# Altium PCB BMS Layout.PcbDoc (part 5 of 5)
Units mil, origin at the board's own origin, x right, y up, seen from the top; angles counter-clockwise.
Board outline 5576.78 x 4051.82 mil, 6 copper layers (Top Layer, GND1, Analog Signal, Power, GND2, Bottom Layer), stack 61.2 mil thick; 425 components, 206 nets, 1164 pads, 390 vias.
Unrouted connection lines stored in the file: 32.
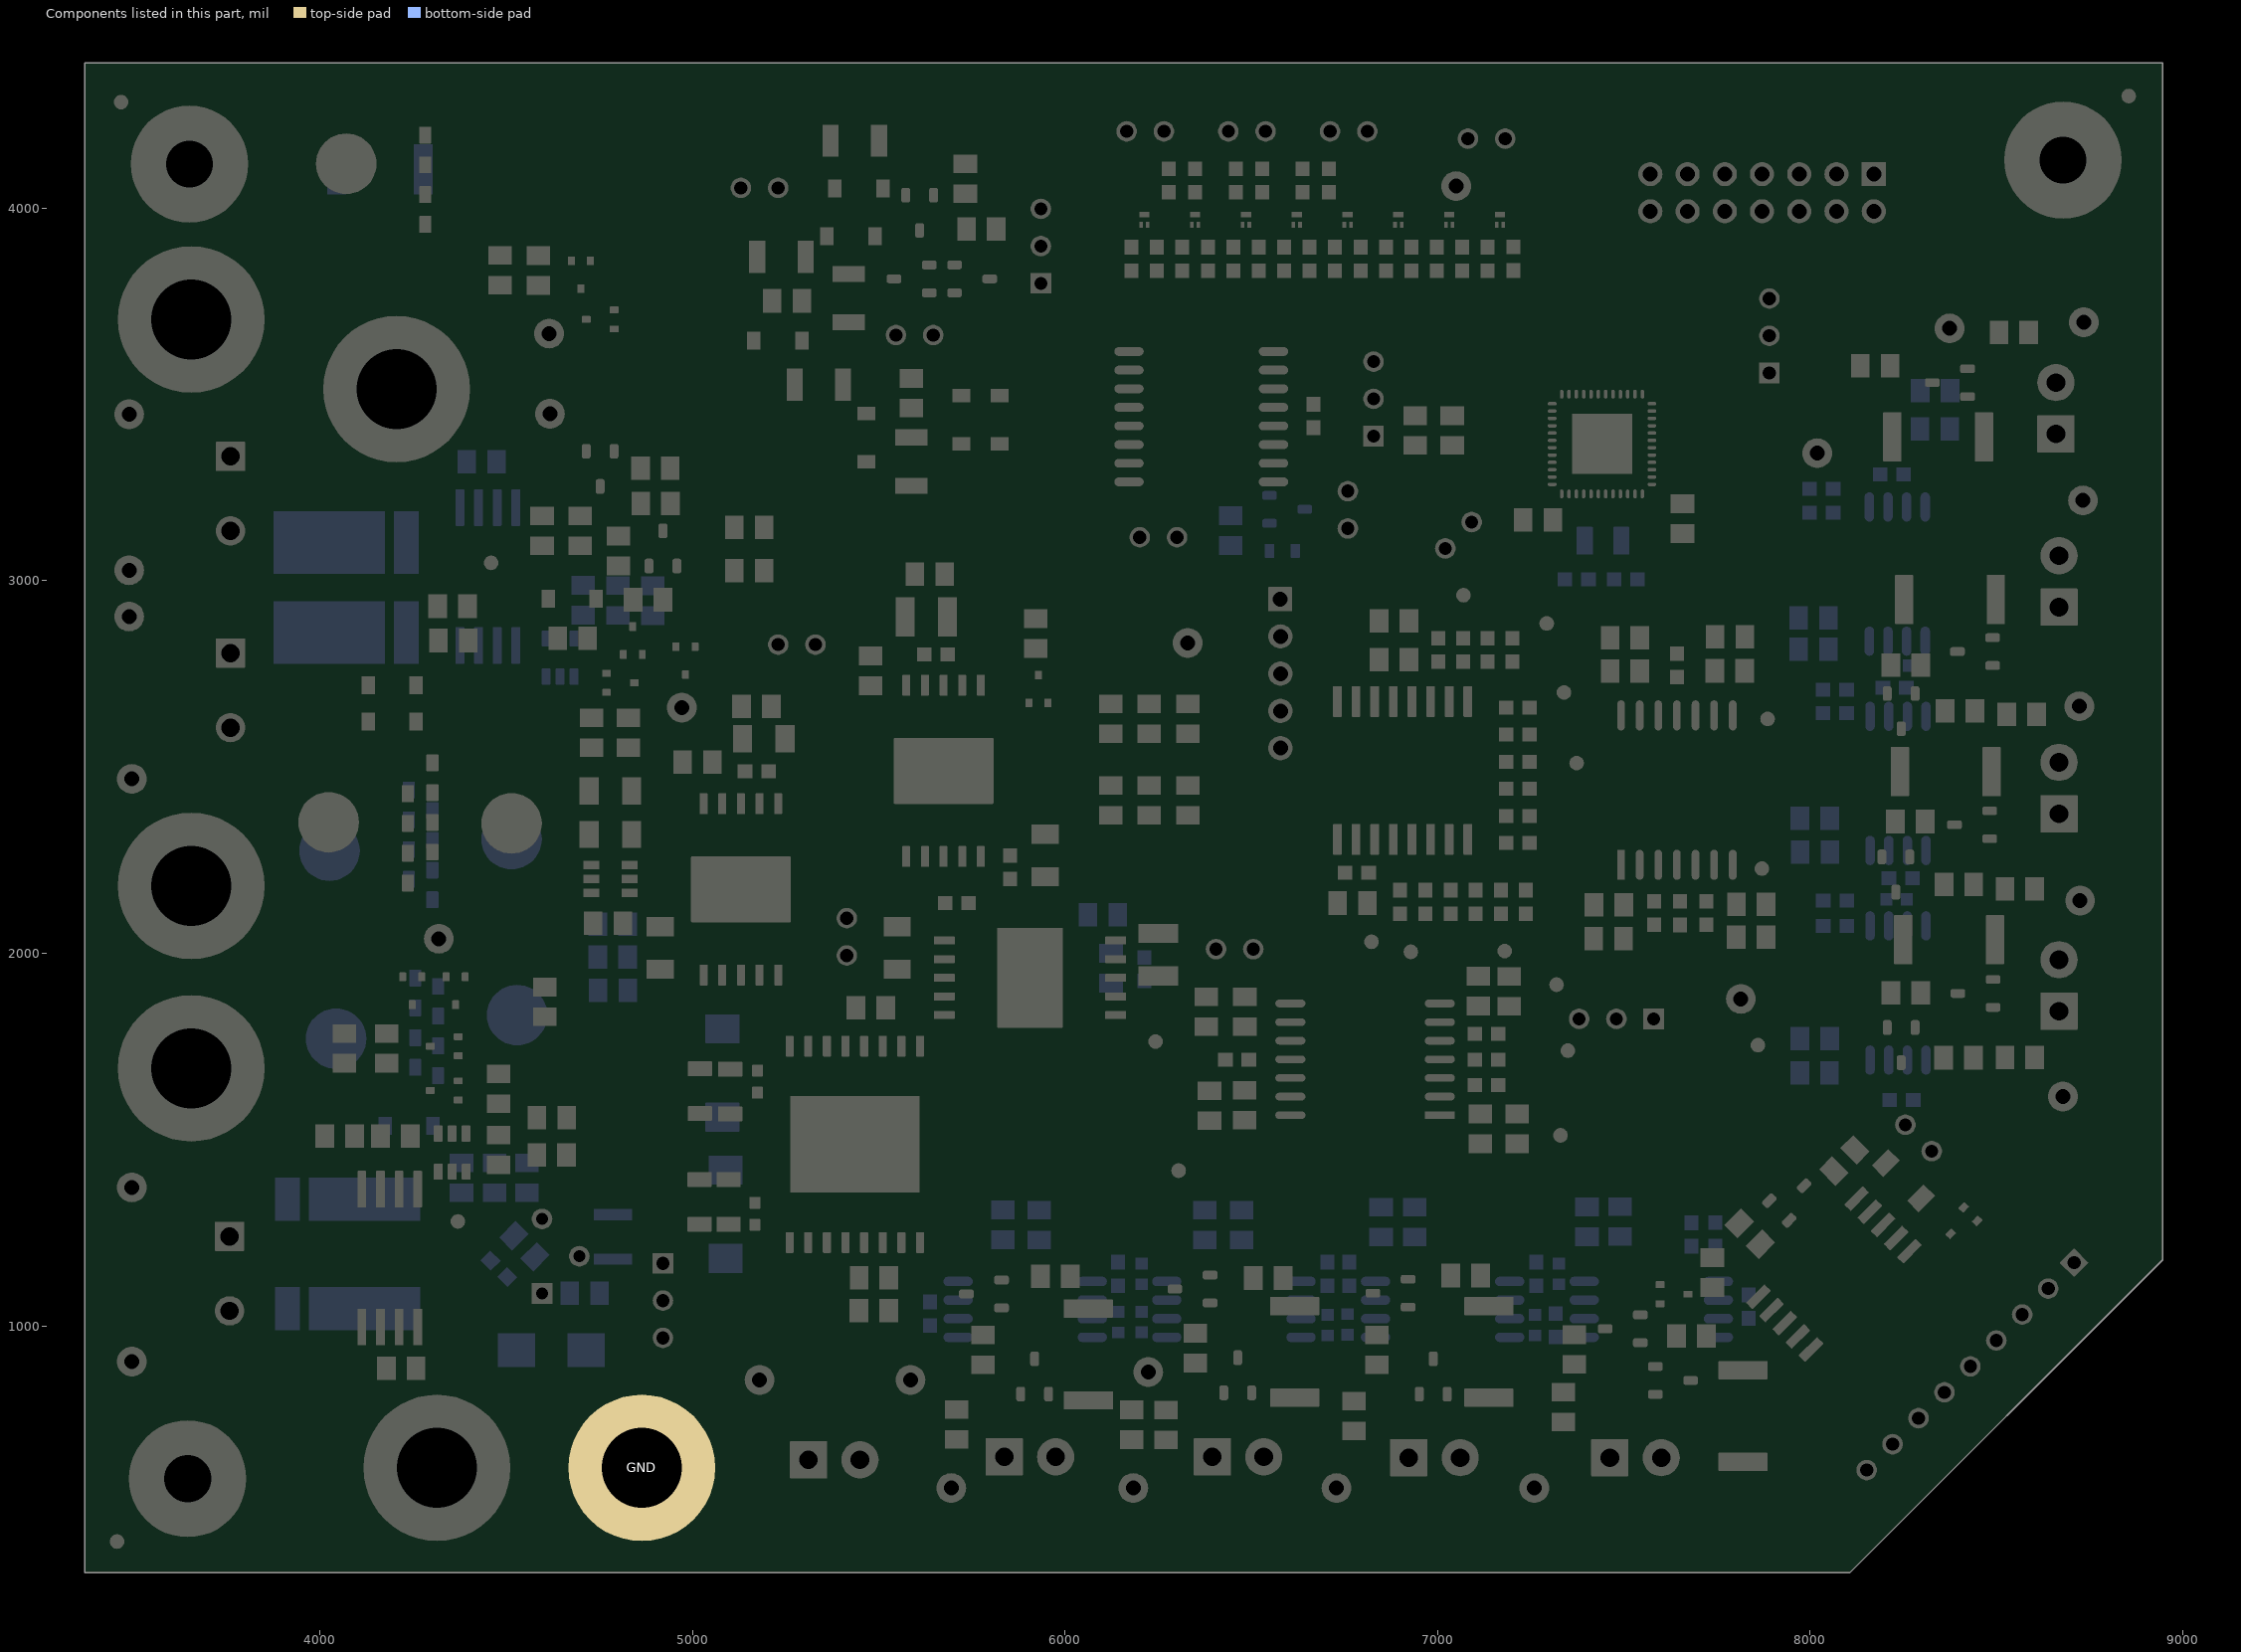
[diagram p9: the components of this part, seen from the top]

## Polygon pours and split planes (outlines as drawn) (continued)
NetC112_1 on Top Layer "NONET_L02_P-001" (solid, pour order 338): 8107.8,1553.93 8059.14,1505.27 8059.14,1476.95 8115.43,1420.67 8115.43,1396.7 8076.94,1358.21 8076.94,1314.64 8097.27,1294.3 8117.24,1294.3 8233.13,1410.2 8329.54,1410.2 8368.39,1449.05 8368.39,1493.65 8345.87,1516.17 8306.13,1516.17 8276.11,1486.14 8216.5,1486.14 8148.71,1553.93
GND on Bottom Layer "NONET_L02_P-001" (solid, pour order 409): 3369.09,4389.76 3369.09,332.49 8102.57,332.49 8949.03,1178.95 8949.03,4389.76
NetLoad_1 on Bottom Layer "NONET_L02_P-001" (solid, pour order 279): 4209.46,4364.27 3394.58,4364.27 3394.58,3274.01 3808.18,3274.01 3939.7,3405.53 3939.7,3639.33 4074.3,3773.93 4209.46,3773.93
NetC15_1 on Bottom Layer "NONET_L02_P-001" (solid, pour order 282): 4414.85,1195.68 4414.85,1159.83 4439.61,1135.07 4467.35,1135.07 4571.68,1239.4 4806.58,1239.4 4851.13,1194.86 4851.13,1144.6 4867.72,1128.01 4958.38,1128.01 4984.96,1154.59 4984.96,1290.46 4935.56,1339.86 4594.88,1339.86 4567.75,1312.73 4531.9,1312.73
Batt1_4V2 on Bottom Layer "NONET_L02_P-001" (solid, pour order 309): 8568.95,1110.98 8568.95,915.98 8618.82,866.12 8636.53,866.12 8946.36,1175.94 8946.36,3325.9 8899.34,3372.91 8633.56,3372.91 8593.4,3332.75 8593.4,3014.55 8651.17,2956.78 8817.01,2956.78 8817.01,2742.63 8817.01,1357.54
Batt3_12V6 on Bottom Layer "NONET_L02_P-001" (solid, pour order 321): 8619.1,2432.66 8596.31,2409.87 8596.31,1971.21 8632.17,1935.35 8712.86,1935.35 8729.63,1918.58 8729.63,1471.59 8401.53,1143.5 8401.53,997.25 8496.21,902.57 8552.86,902.57 8568.95,918.66 8568.95,1110.98 8815.07,1357.1 8815.07,2432.66
Batt7_29V4 on Bottom Layer "NONET_L02_P-001" (solid, pour order 396): 6005.06,693.68 6005.06,344.49 8106.64,344.49 8266.07,498.88 8266.07,730.08 8221.88,731.31 8176.09,685.53 8176.09,573.6 8081.43,478.93 6517.92,478.93 6517.92,693.68
Batt5_21V on Bottom Layer "NONET_L02_P-001" (solid, pour order 398): 7061.47,698.01 7061.47,481.35 7573.87,481.35 7974.06,486.88 8272.26,785.08 8395.72,785.08 8395.72,861.96 8190.67,861.96 7919.96,581.76 7573.87,581.76 7573.87,688.53 7573.87,698.01
Batt_out on Bottom Layer "NONET_L02_P-001" (solid, pour order 407): 3369.77,1463.65 3369.77,340.64 4630.53,340.64 4630.53,1123.97 4553.33,1123.97 4496.73,1067.37 4387.08,1067.37 4255.38,1199.07 3927.91,1199.07 3663.33,1463.65
NetQ23_5 on Bottom Layer "NONET_L02_P-001" (solid, pour order 402): 3866.86,1999.41 3866.86,1517.68 3957.99,1426.55 3957.99,1204.25 4310.2,1204.25 4310.2,1393.05 4240.51,1462.74 4194.72,1462.74 4149.65,1507.81 4149.65,1999.41
NetD6_2 on Bottom Layer "NONET_L02_P-001" (solid, pour order 401): 4192.66,1936.05 4192.66,1657.29 4366.46,1657.29 4366.46,1936.05
NetQ18_5 on Bottom Layer "NONET_L02_P-001" (solid, pour order 399): 3859.99,2976.7 3859.99,2781.91 4358.35,2283.55 4358.35,1622.47 4418.42,1562.4 4681.42,1562.4 4681.42,2647.68 4596.97,2732.14 4231.9,2732.14 4191.01,2773.03 4191.01,2976.22
NetD5_2 on Bottom Layer "NONET_L02_P-001" (solid, pour order 383): 4177.39,2404.64 4177.39,2158.82 4351.18,2158.82 4351.18,2404.64
Charger_Vin on Bottom Layer "NONET_L02_P-001" (solid, pour order 382): 3369.09,2732.14 3369.09,2002.58 4169.29,2002.58 4169.29,2492.69 3929.85,2732.14
NetLoad_2 on Bottom Layer "NONET_L02_P-001" (solid, pour order 380): 4015.86,3754.65 3947.86,3686.65 3947.86,3402.17 3819.69,3274.01 3369.09,3274.01 3369.09,2983.65 4186.55,2983.65 4186.55,3195.31 4291.64,3300.4 4361.16,3300.4 4479.61,3418.84 4479.61,3663.46 4388.41,3754.65
NetC9_1 on Bottom Layer "NONET_L02_P-001" (solid, pour order 375): 5030.82,1867.22 5000.54,1836.95 5000.54,1749.78 5030.3,1720.03 5382.79,1720.03 5461.55,1798.79 5461.55,2019.8 5446.35,2035.01 5385.82,2035.01 5365.03,2014.22 5365.03,1903.77 5328.49,1867.22
12V on Bottom Layer "NONET_L02_P-001" (solid, pour order 351): 4863.79,1125.48 4863.79,1022.32 5208,1022.32 5287.66,1101.99 5356.8,1101.99 5388.67,1133.86 5388.67,1167.2 5314.63,1241.24 4998.33,1241.24 4998.33,1125.48
3.3V on Bottom Layer "NONET_L02_P-001" (solid, pour order 324): 6393.49,3260.28 6384.87,3251.67 6384.87,3152.57 6403.43,3134.01 6482.31,3134.01 6536.66,3188.36 6560.86,3188.36 6583.73,3211.23 6583.73,3247.03 6570.47,3260.28
NetC164_1 on Bottom Layer "NONET_L02_P-001" (solid, pour order 327): 6625.28,3241.77 6587.43,3203.92 6587.43,3058.83 6609.76,3036.51 6649.54,3036.51 6682.54,3069.51 6682.54,3132.62 6741.41,3191.5 6774.14,3191.5 6811.61,3228.97 6811.61,3261.69 6776.91,3296.4 6679.91,3296.4
5Vcc on Power "NONET_L02_P-001" (solid, pour order 336): 4718.34,3982.15 4681.42,3945.23 4681.42,3365.98 4681.42,3319.82 4386.45,3024.85 4386.45,2990.2 4564.24,2812.41 4706.52,2812.41 4706.52,2161.37 4842.97,2161.37 4842.97,1586.01 4483.33,1226.36 4123.45,1586.24 4099.94,1586.24 4023.47,1509.77 4023.47,1278.02 4201.49,1100 4609.68,1100 5335.63,1825.96 6564.85,1825.96 6564.85,2232.96 6538.55,2259.26 6130.5,2259.26 6007.86,2381.89 5521.67,2381.89 5282.73,2620.83 5282.73,3042.25 111903.77,109663.28 5984.25,3776.25 5984.25,3818.73 5820.83,3982.15 5129.42,3982.15
3.3V on Power "NONET_L02_P-001" (solid, pour order 290): 4933.06,2697.61 5984.25,3748.8 5984.25,3855.66 6039.34,3910.75 8157.85,3910.75 8239.99,3828.61 8239.99,3502.43 7778.08,3040.52 7224.26,3040.52 7070.36,3194.41 6344.96,3194.41 5811.38,2660.84 4933.06,2660.84
GND on Power "NONET_L02_P-001" (solid, pour order 363): 3369.09,4389.76 3369.09,332.49 8102.57,332.49 8949.03,1178.95 8949.03,4389.76
pump on Power "NONET_L02_P-001" (solid, pour order 335): 4399.61,4389.76 4399.61,3329.52 4065.85,2995.76 4065.85,1984.18 4323.23,1984.18 4323.23,2709.54 4600.61,2709.54 4600.61,2658.07 4681.42,2658.07 4681.42,2812.41 4553.16,2812.41 4382.25,2983.32 4382.25,3020.65 4681.42,3319.82 4681.42,3945.23 4718.34,3982.15 5129.42,3982.15 5178.86,4031.59 5178.86,4388.07 5177.17,4389.76
Batt_out on Power "NONET_L02_P-001" (solid, pour order 360): 3366.14,1454.17 3836.64,1454.17 4190.81,1100 5570.87,1100 5570.87,796.15 5996.59,796.15 5996.59,338.23 3366.14,334.65
NetQ18_5 on Power "NONET_L02_P-001" (solid, pour order 320): 4600.61,2709.54 4323.23,2709.54 4323.23,1944.18 4646.66,1944.18 4646.66,2649.24 4600.61,2649.24
2.5Vref on Power "NONET_L02_P-001" (solid, pour order 287): 8132.4,3343.71 7609.85,2821.16 7609.85,2219.73 7658.46,2171.12 7658.46,2089.44 7639.88,2070.86 7611.34,2070.86 7558.69,2123.5 7504.65,2123.5 7283.96,1902.82 7192.79,1902.82 7106.69,1816.71 7106.69,1804.75 7153.27,1758.17 7153.27,1734.66 7118.69,1700.08 6767.69,1700.08 6641.81,1825.96 5570.87,1825.96 5570.87,797.87 8553.78,797.87 8937.01,1181.1 8937.01,3343.71
5Vcc on Power "NONET_L02_P-001" (solid, pour order 288): 6386.69,2108.69 6386.69,1825.96 6641.81,1825.96 6767.69,1700.08 7120.52,1700.08 7148.31,1727.87 7148.31,1764.96 7146.48,1764.96 7106.69,1804.75 7106.69,1816.71 7107.32,1816.71 7193.42,1902.82 7283.96,1902.82 7504.65,2123.5 7558.69,2123.5 7611.34,2070.86 7639.88,2070.86 7658.46,2089.44 7658.46,2171.12 7609.85,2219.73 6497.73,2219.73
3.3V_2 on Power "NONET_L02_P-001" (solid, pour order 289): 6682.41,3186.17 6682.41,2990.78 6771.73,2901.46 6933.63,2901.46 7102.41,3070.23 7102.41,3186.17
GND on Analog Signal "NONET_L02_P-001" (solid, pour order 348): 3369.09,4389.76 3369.09,332.49 8102.57,332.49 8949.03,1178.95 8949.03,4389.76
12Vcc on Analog Signal "NONET_L02_P-001" (solid, pour order 291): 5386.85,2202.85 5322.1,2138.11 5322.1,2070.28 5322.1,344.49 8100.39,344.49 8937.01,1181.1 8937.01,3177.02 8907.15,3206.87 7978.82,3206.87 7946.41,3174.46 7946.41,1743.31 7570.03,1366.92 5864.27,1366.92 5786.92,1444.27 5786.92,2138.23 5722.29,2202.85
0V6 on Analog Signal "NONET_L02_P-001" (solid, pour order 339): 4544.02,2953.26 4544.02,2857.18 4557.02,2844.18 4634.08,2844.18 4716.95,2927.06 5086.84,2927.06 5127.2,2967.42 5127.2,3108.26 5114.09,3121.37 4712.13,3121.37
0.6V on Analog Signal "NONET_L02_P-001" (solid, pour order 337): 4185.73,1453.16 4185.73,1354.08 4201.03,1338.79 4544.09,1338.79 4814.16,1608.85 4814.16,2252.33 4707.19,2252.33 4655.26,2200.41 4655.26,1922.7
GND on GND1 "NONET_L02_P-001" (solid, pour order 344): 3369.09,4389.76 3369.09,332.49 8102.57,332.49 8949.03,1178.95 8949.03,4389.76
GND on GND1 "NONET_L02_P-001" (solid, pour order 154): 3369.09,4389.76 3369.09,332.49 8102.57,332.49 8949.03,1178.95 8949.03,4389.76
GND on GND2 "NONET_L02_P-001" (solid, pour order 155): 3369.09,4389.76 3369.09,332.49 8102.57,332.49 8949.03,1178.95 8949.03,4389.76

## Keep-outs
Keep-Out Layer:
  text ".Layer_Name" at 577,-858.49 h60

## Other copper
Top Layer:
  text ".Layer_Name" at 577,-858.49 h60
Bottom Layer:
  text ".Layer_Name" at 577,-858.49 h60

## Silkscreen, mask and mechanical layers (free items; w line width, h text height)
Top Overlay:
  text "GND" at 7123.96,4247.09 h60 r90
  text "D-               D-               D-" at 6245.51,4228.18 h60
  text "TX /  /  / RX" at 7545.33,3861.77 h40 r270
  text "12V /  /  / Buff /  /  / 5V" at 5981.94,3761.49 h40
  text "VCC_Target /  /  / 3V3 /  /  / VCC_Tool" at 7619.85,3541.54 h40
  text "GND /  /  /   SEL  /  /  /   SDA" at 6574.17,3363.19 h40
  text "- /  /  / +" at 3508.51,3006.52 h40
  text "DIN /  /  / DOUT /  /  / SCLK /  /  / CS /  /  / GND" at 6407.41,2549.79 h40
  text "+ /  /  / -" at 3492.8,2442.42 h40
  text "2.5Vref /  /  / ADCin /  /  / Vsens5" at 7286.31,1748.3 h40 r270
  text "Space Graded BMS Design Rev 1" at 6098.29,1268.78 h90
  text "+ /  /  / -" at 3468.21,1003.43 h40
  text "12V_LDO /  /  / Sel /  /  / 12V_Supply" at 4998.33,894.25 h40
  text "+ /  /  / -" at 5526.97,388.03 h40 r90
  text "'.PRJ_Number'.PCB_Rev" at 2383.2,147.04 h108.27
  text "Drill Drawing Layer...they should be just to the right of your board shape" at 6663.39,-275.59 h60
  text ".Layer_Name" at 577,-858.49 h60
Bottom Overlay:
  text ".Layer_Name" at 577,-858.49 h60
Top Paste:
  text ".Layer_Name" at 577,-858.49 h60
Bottom Paste:
  text ".Layer_Name" at 577,-858.49 h60
Top Solder:
  text ".Layer_Name" at 577,-858.49 h60
  text ".Layer_Name" at 577,-858.49 h60
Bottom Solder:
  text ".Layer_Name" at 577,-858.49 h60
Drill Guide:
  text ".Layer_Name" at 577,-858.49 h60
M1 Board Outline:
  text ".Layer_Name" at 577,-858.49 h60
M2 Board Dimensions:
  rectangle: 0,-275 125,-150
  rectangle: 125,-400 500,-275
  lines w7: 0,-275 1000,-275 ; 0,-150 0,-400 1000,-400 1000,-150 ; 125,-400 125,-150 ; 250,-400 250,-150 ; 500,-400 500,-150 ; 750,-400 750,-150
  text ".Layer_Name" at 577,-858.49 h60
M3 3D STEP Top:
  text ".Layer_Name" at 577,-858.49 h60
M4 3D STEP Bottom:
  text ".Layer_Name" at 577,-858.49 h60
M5 Assembly Top:
  lines w10: -292,-930.17 6308,-930.17 ; -292,-726.83 6310,-726.83 ; -292,-523.5 -292,-1133.5 3713,-1133.5 6310,-1133.5 6310,-523.5 -291.5,-523.5 -291.5,-1133.5 1284,-1133.5 ; 2173,-1133.5 2173,-523.5 ; 3440,-726.83 3440,-523.5 ; 4280,-726.83 4280,-523.5 ; 4902,-1140 4902,-937.17
  text "COMPONENTS MARKED 'DNP' SHOULD NOT BE POPULATED." at 1153.5,-318.5 h60
  text "ASSEMBLY VARIANT:" at 1153,-434 h60
  text ".VariantName" at 2189,-434 h60
  text "PCB VIEWED FROM TOP SIDE" at -228.5,-655.67 h60
  text "BOARD #:" at 2248,-655.67 h60
  text ".PRJ_Number" at 2793.5,-655.67 h60
  text "REV:" at 3638,-655.67 h60
  text ".PCB_Rev" at 3929.5,-655.67 h60
  text "SVN REV:" at 4476,-655.67 h60
  text ".VersionControl_RevNumber" at 4982,-655.67 h60
  text "TID #:" at 2248,-859 h60
  text ".TID" at 2793.5,-859 h60
  text "PLOT NAME =" at -228.5,-1064.34 h60
  text ".plot_File_Name" at 577,-1064.34 h60
  text "GENERATED    :" at 2250,-1064.34 h60
  text ".Print_Date" at 3119.5,-1064.34 h60
  text ".Print_Time" at 3848.5,-1064.34 h60
  text "TEXAS INSTRUMENTS" at 5113,-1064.34 h60
M6 Assembly Bottom:
  lines w10: -292.5,-727.33 6309.5,-727.33 ; -290.5,-930.67 6309.5,-930.67 ; 1115.5,-1140.5 1115.5,-937.67 ; 1737.5,-727.33 1737.5,-524 ; 2577.5,-727.33 2577.5,-524 ; 3844.5,-1134 3844.5,-524 ; 4733.5,-1134 6309,-1134 6309,-524 -292.5,-524 -292.5,-1134 2304.5,-1134 6309.5,-1134 6309.5,-524
  text "COMPONENTS MARKED 'DNP' SHOULD NOT BE POPULATED." at 6102,-318 h60
  text ".VariantName" at 5058,-434 h60
  text "ASSEMBLY VARIANT:" at 6097,-434 h60
  text ".VersionControl_RevNumber" at 1035.5,-656.17 h60
  text "SVN REV:" at 1541.5,-656.17 h60
  text ".PCB_Rev" at 2088,-656.17 h60
  text "REV:" at 2379.5,-656.17 h60
  text ".PRJ_Number" at 3224,-656.17 h60
  text "BOARD #:" at 3769.5,-656.17 h60
  text "PCB VIEWED FROM BOTTOM SIDE" at 6246,-656.17 h60
  text ".TID" at 3224,-859.5 h60
  text "TID #:" at 3769.5,-859.5 h60
  text "TEXAS INSTRUMENTS" at 904.5,-1064.84 h60
  text ".Print_Time" at 2169,-1064.84 h60
  text ".Print_Date" at 2898,-1064.84 h60
  text "GENERATED    :" at 3767.5,-1064.84 h60
  text ".plot_File_Name" at 5440.5,-1064.84 h60
  text "PLOT NAME =" at 6246,-1064.84 h60
M9 Title Sheet:
  drawing of 57 lines, arcs and shapes, not listed
  text "1" at 739.84,8036.5 h70
  text "2" at 3235.5,8036.5 h70
  text "3" at 5724.84,8036.5 h70
  text "4" at 8231.51,8036.5 h70
  text "5" at 10730.5,8036.5 h70
  text "6" at 13235.5,8036.5 h70
  text "A" at -416.5,6893.5 h70
  text "A" at 14383.5,6893.5 h70
  text "B" at -416.5,4513.5 h70
  text "B" at 14383.5,4513.5 h70
  text "C" at -416.5,2138.5 h70
  text "C" at 14383.5,2138.5 h70
  text "PROJECT TITLE:" at 11343.5,277.5 h45
  text ".PRJ_Title" at 11393.5,144.17 h70
  text "DESIGNED FOR:" at 11343.5,-23.5 h45
  text ".PRJ_Customer" at 11393.5,-163.5 h70
  text "D" at -416.5,-231.5 h70
  text "D" at 14383.5,-231.5 h70
  text "FILE NAME:" at 11343.5,-323.5 h45
  text ".PCB_File_Name_No_Path" at 11393.5,-443.5 h70
  text "Texas Instruments (TI) and/or its licensors do not warrant the accuracy or completeness of this specification" at 6374,-605.34 h45
  text "ENGINEER:" at 11343.5,-613.5 h45
  text "LAYOUT BY:" at 12848.5,-613.5 h45
  text "or any information contained therein. TI and/or its licensors do not warrant that this design will meet" at 6329.01,-718 h45
  text ".PRJ_Engineer" at 11393.5,-768.49 h70
  text ".PCB_Layout" at 12899,-768.49 h70
  text "the specifications, will be suitable for your application or fit for any particular purpose, or will operate in" at 6329.01,-830.67 h45
  text ".Layer_Name" at 577,-858.49 h60
  text "ALTIUM DESIGNER VERSION:" at 12848.5,-923.5 h45
  text "an implementation. TI and/or its licensors do not warrant that the design is production worthy. You should" at 6329.01,-943.33 h45
  text "completely validate and test your design implementation to confirm the system functionality for your application." at 6374,-1056 h45
  text ".print_Scale" at 11393.5,-1056.83 h70
  text ".Application_BuildNumber" at 12899,-1056.83 h70
  text "1" at 739.84,-1263.5 h70
  text "2" at 3235.5,-1263.5 h70
  text "3" at 5724.84,-1263.5 h70
  text "4" at 8231.51,-1263.5 h70
  text "5" at 10730.5,-1263.5 h70
  text "6" at 13235.5,-1263.5 h70
M10 Fab Notes:
  drawing of 189 lines, arcs and shapes, not listed
  text "DESIGN INFORMATION" at 12382.02,6356.17 h60
  text "MIN. TRACK WIDTH:" at 11737.46,6224.05 h60
  text "8" at 12833.7,6224.05 h60
  text "MIL" at 12988.46,6224.05 h60
  text "7.874" at 12667.32,6102.36 h60
  text "MIN. CLEARANCE:" at 11737.46,6099.92 h60
  text "MIL" at 12988.46,6099.92 h60
  text "MIN. VIA PAD SIZE:" at 11737.46,5975.8 h60
  text "24" at 12803.71,5975.8 h60
  text "MIL" at 12988.46,5975.8 h60
  text "0.05mm (2MIL)" at 12432.46,5845.9 h60
  text "MINIMUM ANNULAR RING" at 11408.23,5837.67 h60
  text "EXTERNAL" at 13140.46,5837.67 h60
  text "PER" at 11608.23,5727.55 h60
  text "IPC-D-275 CLASS 2 LEVEL C" at 11828.23,5727.54 h60
  text "MIL, HOLES" at 13316.46,5627.07 h60
  text "+/-" at 12924,5618.48 h60
  text "+/-" at 13778,5618.48 h60
  text "REGISTRATION TOLERANCES:" at 11408.23,5617.42 h60
  text "METAL" at 12608,5617.42 h60
  text "5" at 13184.2,5617.42 h60
  text "3" at 14017.2,5617.42 h60
  text "MIL" at 14133.46,5617.42 h60
  text "HOLE SIZE TOLERANCE (UNLESS OTHERWISE SPECIFIED):" at 11408.23,5519.1 h60
  text "+/-" at 13778,5516.23 h60
  text "3" at 14017.2,5515.17 h60
  text "MIL" at 14133.46,5515.17 h60
  text "MATERIAL:" at 11333.46,5377.52 h60
  text "FR-4 High Tg" at 12319.9,5249 h60
  text "X" at 12175.46,5241.01 h60
  text "FR-408" at 11754.46,5236.49 h60
  text "OTHER" at 13242.46,5236.49 h60
  text "62 MIL (1.6mm) +/-10%" at 12074.56,5093.46 h60
  text "X" at 11954.46,5091.01 h60
  text "THICKNESS:" at 11408.23,5085.24 h60
  text "OTHER" at 13359.46,5085.24 h60
  text "TOLERANCE:" at 11408.23,4946.92 h60
  text "X" at 12256.46,4946.92 h60
  text "ANSI IPC-6012 TYPE 3 CLASS 2" at 12434.48,4946.92 h60
  text "OTHER +/-" at 12434.46,4802.73 h60
  text "BOW & TWIST:" at 11408.23,4657.54 h60
  text "X" at 12256.46,4657.54 h60
  text "ANSI IPC-6012 TYPE 3 CLASS 2" at 12434.48,4657.54 h60
  text "OTHER +/-" at 12434.46,4510.85 h60
  text "DRILLING:" at 11333.46,4380.23 h60
  text "NC_DRILL FILES" at 13094.46,4275.04 h60
  text "REFERENCE:" at 11408.23,4271.1 h60
  text "X" at 12065.46,4271.01 h60
  text "AS SHOWN" at 12243.46,4271.1 h60
  text "X" at 12966.46,4271.1 h60
  text "OTHER" at 13392.46,4128.85 h60
  text "PTH COPPER THICKNESS:" at 11407.91,4125.32 h60
  text "X" at 12547.14,4125.32 h60
  text "20-30 um" at 12675.14,4125.32 h60
  text "BOARD FINISH:" at 11333.46,3977.73 h60
  text "SILKSCREEN:" at 11488.68,3867.6 h60
  text "X" at 12446.46,3867.6 h60
  text "TOP" at 12563.46,3867.6 h60
  text "X" at 12956.46,3867.6 h60
  text "BOTTOM" at 13074.46,3867.6 h60
  text "SILKSCREEN COLOR:" at 11488.68,3712.41 h60
  text "X" at 12445.46,3712.41 h60
  text "WHITE" at 12563.46,3712.41 h60
  text "OTHER" at 13074.46,3712.41 h60
  text "X" at 12576.46,3568.96 h60
  text "GREEN" at 12694.46,3568.96 h60
  text "OTHER" at 13312.46,3568.96 h60
  text "SOLDER RESIST COLOR:" at 11488.68,3562.1 h60
  text "X" at 12576.46,3414.71 h60
  text "MATTE" at 12694.46,3414.71 h60
  text "SEMI-GLOSS" at 13312,3414.07 h60
  text "IMMERSION GOLD (ENIG)" at 12394.46,3241.94 h60
  text "ENEPIG" at 13732,3234.72 h60
  text "SURFACE FINISH:" at 11333.46,3233.72 h60
  text "X" at 12216.46,3233.72 h60
  text "IMM. TIN/SILVER OR EQUIV" at 11663,3096.4 h60
  text "OTHER" at 13094.46,3092.47 h60
  text "ARRAY/PANEL:" at 11333.46,2937.09 h60
  text "CUT AND TRIM PER M1 BOARD OUTLINE" at 12394.46,2928.87 h60
  text "N.C. ROUTE" at 12394.46,2792.9 h60
  text "X" at 13082.46,2792.9 h60
  text "V. SCORE" at 13260.46,2792.9 h60
  text "CERTIFICATION:" at 11333.46,2663.77 h60
  text "MATERIALS AND WORKMANSHIP FOR ALL PCBS" at 12058.46,2663.77 h60
  text "TO MEET OR EXCEED THE REQUIREMENTS OF:" at 12058.46,2569.71 h60
  text "X" at 11695.97,2441.08 h60
  text "ANSI IPC-A-600F CLASS ->" at 11823.96,2441.08 h60
  text "X" at 13471.97,2441.08 h60
  text "2" at 13581.96,2441.08 h60
  text "1" at 13266.96,2439.58 h60
  text "3" at 13935.96,2439.58 h60
  text "X" at 12507.97,2293.39 h60
  text "RoHS" at 12635.96,2293.39 h60
  text "OTHER" at 13280.36,2293.39 h60
  text "PER ORDER" at 13677.42,2293.39 h60
  text "ALL BOARDS MUST MEET OR EXCEED UL94-V0 REQUIREMENTS." at 11361,2139.57 h60
  text "PCB MUST BEAR THE UL94V-0 UL REGISTERED MATERIAL ID NUMBER" at 11361,2023.5 h60
  text "ADDITIONAL REQUIREMENTS:" at 11333.46,1854.08 h60
  text "MICROSECTION:" at 11408.23,1746.95 h60
  text "YES" at 12313.96,1746.95 h60
  text "REQUIRED" at 13175.46,1602.62 h60
  text "BARE BOARD ELEC. TEST:" at 11408.23,1599.76 h60
  text "NONE" at 12713.96,1599.76 h60
  text "X" at 13057.46,1599.76 h60
  text "PER ORDER" at 13767.46,1599.76 h60
  text "XX MIL VIAS REQUIRE NON-CONDUCTIVE FILL AND PLANARIZE" at 11576.38,1394.82 h59
  text "XX MIL VIAS REQUIRE CONDUCTIVE FILL AND PLANARIZE" at 11584.38,1290.84 h60
  text "OUTER XX MIL TRACES REQUIRE 50 OHM SINGLE-ENDED IMPEDANCE" at 11583.39,1127.46 h58
  text "LAYER 2 & 3 (INNER LAYERS) XX MIL WIDE, XX MIL SPACE / TRACES REQUIRE 100 OHM DIFFERENTIAL IMPEDANCE" at 11575.39,891.74 h60
  text ".Layer_Name" at 577,-858.49 h60
M11 Gerber Information:
  lines w10: -292,-930.17 6308,-930.17 ; -292,-726.83 6310,-726.83 ; -292,-523.5 -292,-1133.5 3713,-1133.5 6310,-1133.5 6310,-523.5 -291.5,-523.5 -291.5,-1133.5 1284,-1133.5 ; 2173,-1133.5 2173,-523.5 ; 3440,-726.83 3440,-523.5 ; 4280,-726.83 4280,-523.5 ; 4902,-1140 4902,-937.17
  text "ALL ARTWORK VIEWED FROM TOP SIDE" at -228.5,-655.67 h60
  text "BOARD #:" at 2248,-655.67 h60
  text ".PRJ_Number" at 2793.5,-655.67 h60
  text "REV:" at 3638,-655.67 h60
  text ".PCB_Rev" at 3929.5,-655.67 h60
  text "SVN REV:" at 4476,-655.67 h60
  text ".VersionControl_RevNumber" at 4982,-655.67 h60
  text "LAYER NAME =" at -228.5,-858.49 h60
  text "TID #:" at 2248,-859 h60
  text ".TID" at 2793.5,-859 h60
  text "PLOT NAME =" at -228.5,-1064.34 h60
  text ".plot_File_Name" at 577,-1064.34 h60
  text "GENERATED    :" at 2250,-1064.34 h60
  text ".Print_Date" at 3119.5,-1064.34 h60
  text ".Print_Time" at 3848.5,-1064.34 h60
  text "TEXAS INSTRUMENTS" at 5113,-1064.34 h60
M12 Stackup:
  drawing of 264 lines, arcs and shapes, not listed
  text "Layer" at 8922.6,7835.43 h60
  text "Name" at 9173.69,7835.43 h60
  text "Material" at 9659.27,7835.43 h60
  text "Thickness" at 10095.62,7835.43 h60
  text "Constant" at 10454.05,7835.43 h60
  text "Board Layer Stack" at 10785.78,7835.43 h60
  text "Top Overlay" at 9173.69,7715.43 h60
  text "Top Solder" at 9173.69,7595.43 h60
  text "Solder Resist" at 9659.27,7595.43 h60
  text "0.40mil" at 10095.62,7595.43 h60
  text "3.5" at 10454.05,7595.43 h60
  text "1" at 8922.6,7475.43 h60
  text "Top Layer" at 9173.69,7475.43 h60
  text "2.76mil" at 10095.57,7475.43 h60
  text "Dielectric 1" at 9173.69,7355.43 h60
  text "PP-006" at 9659.27,7355.43 h60
  text "2.80mil" at 10095.57,7355.43 h60
  text "4.1" at 10454.05,7355.43 h60
  text "2" at 8922.55,7235.43 h60
  text "GND1" at 9173.69,7235.43 h60
  text "CF-004" at 9659.27,7235.43 h60
  text "1.38mil" at 10095.62,7235.43 h60
  text "Dielectric 3" at 9173.69,7115.43 h60
  text "PP-006" at 9659.27,7115.43 h60
  text "2.80mil" at 10095.57,7115.43 h60
  text "4.1" at 10454.05,7115.43 h60
  text "3" at 8922.6,6995.43 h60
  text "Analog Signal" at 9173.69,6995.43 h60
  text "CF-004" at 9659.27,6995.43 h60
  text "1.38mil" at 10095.62,6995.43 h60
  text "Dielectric1" at 9173.69,6875.43 h60
  text "FR-4 High Tg" at 9659.27,6875.43 h60
  text "38.98mil" at 10095.62,6875.43 h60
  text "4.8" at 10454.05,6875.43 h60
  text "4" at 8922.6,6755.43 h60
  text "Power" at 9173.69,6755.43 h60
  text "CF-004" at 9659.27,6755.43 h60
  text "1.38mil" at 10095.62,6755.43 h60
  text "Dielectric 4" at 9173.69,6635.43 h60
  text "PP-006" at 9659.27,6635.43 h60
  text "2.80mil" at 10095.57,6635.43 h60
  text "4.1" at 10454.05,6635.43 h60
  text "5" at 8922.6,6515.43 h60
  text "GND2" at 9173.69,6515.43 h60
  text "CF-004" at 9659.27,6515.43 h60
  text "1.38mil" at 10095.62,6515.43 h60
  text "Dielectric 2" at 9173.69,6395.43 h60
  text "PP-006" at 9659.27,6395.43 h60
  text "2.80mil" at 10095.57,6395.43 h60
  text "4.1" at 10454.05,6395.43 h60
  text "6" at 8922.6,6275.43 h60
  text "Bottom Layer" at 9173.69,6275.43 h60
  text "2.76mil" at 10095.57,6275.43 h60
  text "Bottom Solder" at 9173.69,6155.43 h60
  text "Solder Resist" at 9659.27,6155.43 h60
  text "0.40mil" at 10095.62,6155.43 h60
  text "3.5" at 10454.05,6155.43 h60
  text "Bottom Overlay" at 9173.69,6035.43 h60
  text ".Layer_Name" at 577,-858.49 h60
M13 Component Bodies Top:
  text ".Layer_Name" at 577,-858.49 h60
M14 Component Bodies Bottom:
  text ".Layer_Name" at 577,-858.49 h60
M15 Courtyards Top:
  text ".Layer_Name" at 577,-858.49 h60
M16 Courtyards Bottom:
  text ".Layer_Name" at 577,-858.49 h60
Drill Drawing:
  drawing of 184 lines, arcs and shapes, not listed
  text "Symbol" at 5753.69,7841.72 h70.1
  text "Quantity" at 6046.47,7841.72 h70.1
  text "Finished Hole Size" at 6369.89,7841.72 h70.1
  text "Plated" at 6990.09,7841.72 h70.1
  text "Hole Type" at 7242.5,7841.72 h70.1
  text "Drill Layer Pair" at 7607.97,7841.72 h70.1
  text "Hole Tolerance" at 8312.73,7841.72 h70.1
  text "93" at 6046.47,7720.76 h58.42
  text "7.87mil (0.200mm)" at 6369.89,7720.76 h58.42
  text "PTH" at 6990.09,7720.76 h58.42
  text "Round" at 7242.5,7720.76 h58.42
  text "Top Layer - Bottom Layer" at 7607.97,7720.76 h58.42
  text "10" at 6046.47,7599.8 h58.42
  text "8.00mil (0.203mm)" at 6369.89,7599.8 h58.42
  text "PTH" at 6990.09,7599.8 h58.42
  text "Round" at 7242.5,7599.8 h58.42
  text "Top Layer - Bottom Layer" at 7607.97,7599.8 h58.42
  text "113" at 6046.47,7478.84 h58.42
  text "10.00mil (0.254mm)" at 6369.89,7478.84 h58.42
  text "PTH" at 6990.09,7478.84 h58.42
  text "Round" at 7242.5,7478.84 h58.42
  text "Top Layer - Bottom Layer" at 7607.97,7478.84 h58.42
  text "104" at 6046.47,7357.88 h58.42
  text "12.00mil (0.305mm)" at 6369.89,7357.88 h58.42
  text "PTH" at 6990.09,7357.88 h58.42
  text "Round" at 7242.5,7357.88 h58.42
  text "Top Layer - Bottom Layer" at 7607.97,7357.88 h58.42
  text "7" at 6046.47,7236.92 h58.42
  text "13.00mil (0.330mm)" at 6369.89,7236.92 h58.42
  text "PTH" at 6990.09,7236.92 h58.42
  text "Round" at 7242.5,7236.92 h58.42
  text "Top Layer - Bottom Layer" at 7607.97,7236.92 h58.42
  text "2" at 6046.47,7115.96 h58.42
  text "14.00mil (0.356mm)" at 6369.89,7115.96 h58.42
  text "PTH" at 6990.09,7115.96 h58.42
  text "Round" at 7242.5,7115.96 h58.42
  text "Top Layer - Bottom Layer" at 7607.97,7115.96 h58.42
  text "3" at 6046.47,6995 h58.42
  text "16.00mil (0.406mm)" at 6369.89,6995 h58.42
  text "PTH" at 6990.09,6995 h58.42
  text "Round" at 7242.5,6995 h58.42
  text "Top Layer - Bottom Layer" at 7607.97,6995 h58.42
  text "58" at 6046.47,6874.04 h58.42
  text "18.00mil (0.457mm)" at 6369.89,6874.04 h58.42
  text "PTH" at 6990.09,6874.04 h58.42
  text "Round" at 7242.5,6874.04 h58.42
  text "Top Layer - Bottom Layer" at 7607.97,6874.04 h58.42
  text "3" at 6046.47,6753.08 h58.42
  text "31.50mil (0.800mm)" at 6369.89,6753.08 h58.42
  text "PTH" at 6990.09,6753.08 h58.42
  text "Round" at 7242.5,6753.08 h58.42
  text "Top Layer - Bottom Layer" at 7607.97,6753.08 h58.42
  text "50" at 6046.47,6632.12 h58.42
  text "35.43mil (0.900mm)" at 6369.89,6632.12 h58.42
  text "PTH" at 6990.09,6632.12 h58.42
  text "Round" at 7242.5,6632.12 h58.42
  text "Top Layer - Bottom Layer" at 7607.97,6632.12 h58.42
  text "46" at 6046.47,6511.16 h58.42
  text "40.00mil (1.016mm)" at 6369.89,6511.16 h58.42
  text "PTH" at 6990.09,6511.16 h58.42
  text "Round" at 7242.5,6511.16 h58.42
  text "Top Layer - Bottom Layer" at 7607.97,6511.16 h58.42
  text "6" at 6046.47,6390.2 h58.42
  text "49.21mil (1.250mm)" at 6369.89,6390.2 h58.42
  text "PTH" at 6990.09,6390.2 h58.42
  text "Round" at 7242.5,6390.2 h58.42
  text "Top Layer - Bottom Layer" at 7607.97,6390.2 h58.42
  text "18" at 6046.47,6269.24 h58.42
  text "50.00mil (1.270mm)" at 6369.89,6269.24 h58.42
  text "PTH" at 6990.09,6269.24 h58.42
  text "Round" at 7242.5,6269.24 h58.42
  text "Top Layer - Bottom Layer" at 7607.97,6269.24 h58.42
  text "3" at 6046.47,6148.28 h58.42
  text "125.98mil (3.200mm)" at 6369.89,6148.28 h58.42
  text "PTH" at 6990.09,6148.28 h58.42
  text "Round" at 7242.5,6148.28 h58.42
  text "Top Layer - Bottom Layer" at 7607.97,6148.28 h58.42
  text "6" at 6046.47,6027.32 h58.42
  text "214.57mil (5.450mm)" at 6369.89,6027.32 h58.42
  text "PTH" at 6990.09,6027.32 h58.42
  text "Round" at 7242.5,6027.32 h58.42
  text "Top Layer - Bottom Layer" at 7607.97,6027.32 h58.42
  text "522 Total" at 6046.47,5906.36 h58.42
  text ".Layer_Name" at 577,-858.49 h60
M17 Embedded Cavity:
  text ".Layer_Name" at 577,-858.49 h60
M18 Embedded Assembly:
  text ".Layer_Name" at 577,-858.49 h60
M19 Embedded Keepout:
  text ".Layer_Name" at 577,-858.49 h60

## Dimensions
3369.09,337.94 to 8949.03,332.49 on M1 Board Outline
3369.09,4389.76 to 3369.09,337.94 on M1 Board Outline
0,-400 to 1000,-400 on M2 Board Dimensions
